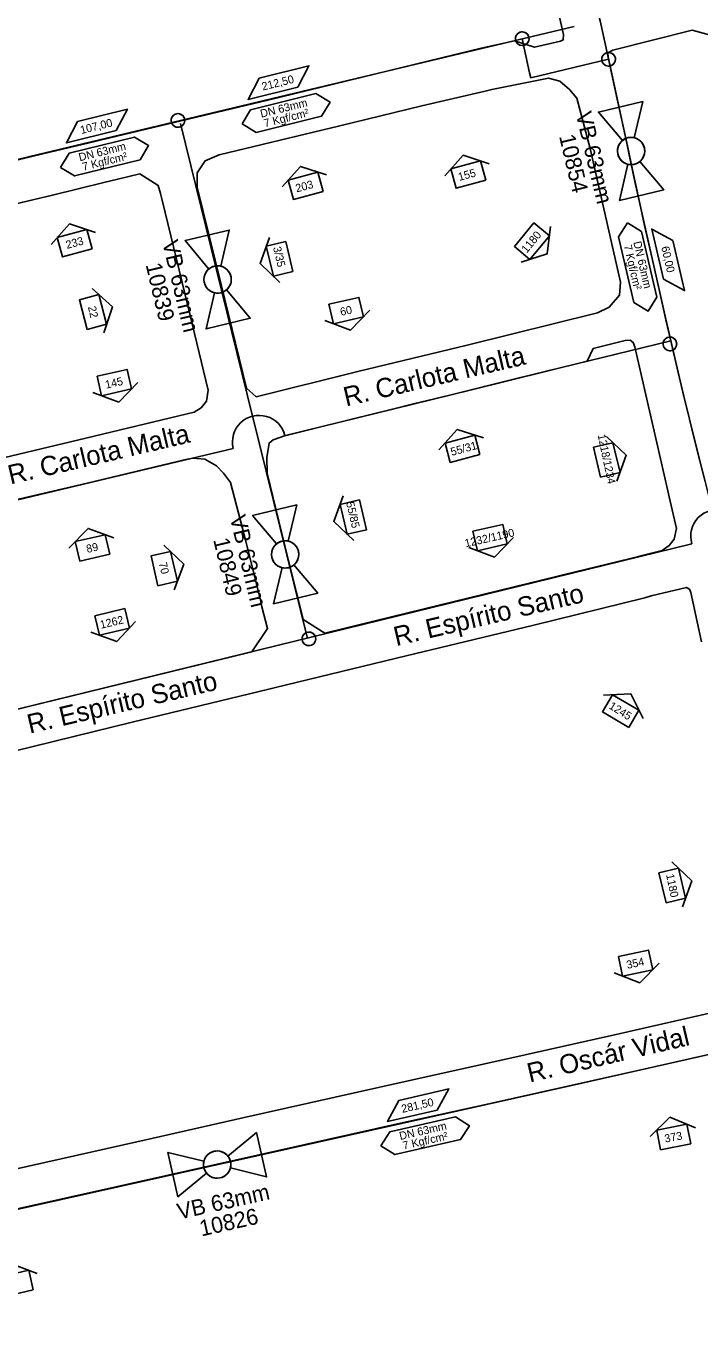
# Model space of a CAD drawing. Extents: x 656692 to 673945, y 7585994 to 7599066.
# Drawn here: x 669777.5 to 670030, y 7593096.2 to 7593583.8 of the extents above; entities that cross this region are included whole.
import ezdxf

# ---------------------------------------------------------------- set-up
doc = ezdxf.new("R2010")
doc.units = 0
for name, color, linetype in [('FORMATO', 7, 'Continuous'), ('LOGRADOURO', 7, 'Continuous'), ('LOGRADOURO_TEXTO', 7, 'Continuous'), ('NUM_REF', 7, 'Continuous'), ('SIMBOLO', 7, 'Continuous'), ('TEXTO', 7, 'Continuous'), ('TUBO_PEAD_GN_63', 7, 'Continuous'), ('VALVULA_PEAD_63', 7, 'Continuous')]:
    doc.layers.add(name, color=color, linetype=linetype)

# ---------------------------------------------------------------- blocks, each defined once
blk = doc.blocks.new('INTERLIGACAO_5')
at = {"layer": 'SIMBOLO'}
blk.add_circle((0, 0), 1.28, dxfattribs=at)
for start, end in [(0, 180), (180, 0)]:
    blk.add_arc((0, 0), 1.28, start, end, dxfattribs=at)
blk = doc.blocks.new('VALVULA_PEAD_DN_9')
at = {"layer": 'VALVULA_PEAD_63'}
for points in [[(-1.14, 0.57), (-4.25, 2.13), (-4.25, -2.13), (-1.14, -0.57)], [(-1.14, -0.57), (-4.25, -2.13), (-4.25, 2.13), (-1.14, 0.57)], [(1.14, -0.57), (4.25, -2.13), (4.25, 2.13), (1.14, 0.57)], [(1.14, -0.57), (4.25, -2.13), (4.25, 2.13), (1.14, 0.57)]]:
    blk.add_lwpolyline(points, dxfattribs=at)
blk.add_circle((0, 0), 1.28, dxfattribs=at)
for start, end in [(90, 270), (270, 90), (153.4349, 206.5651), (0, 26.5651), (333.4349, 0)]:
    blk.add_arc((0, 0), 1.28, start, end, dxfattribs=at)
blk = doc.blocks.new('NUM_REF_1')
at = {"layer": 'NUM_REF'}
blk.add_lwpolyline([(-4.3125, 0.9375), (0, 3.75), (4.3125, 0.9375)], dxfattribs=at)
blk.add_lwpolyline([(2.875, -1.875), (2.875, 1.875), (-2.875, 1.875), (-2.875, -1.875)], close=True, dxfattribs=at)

msp = doc.modelspace()

# ---------------------------------------------------------------- linework, layer by layer
at = {"layer": 'LOGRADOURO'}
msp.add_line((670024.02, 7593444.94), (670031.73, 7593414.01), dxfattribs=at)
for points in [[(669948.03, 7593575.49), (669960.57, 7593578.21), (669968.06, 7593575.91), (669977.72, 7593578.17), (669978.78, 7593578.62), (669978.93, 7593580.62), (669975.67, 7593594.92), (669968.75, 7593625.45), (669962.29, 7593653.78), (669956.77, 7593677.72)], [(670035.32, 7593580.07), (670027.12, 7593582.27), (669997.35, 7593574.79), (669995.49, 7593573.74), (669995.57, 7593572.26), (670002.69, 7593539.31), (670003.33, 7593536.19), (670005.61, 7593525.54), (670017.19, 7593473.94), (670024.02, 7593444.94)], [(669948.03, 7593575.49), (669868.09, 7593556.09), (669808.81, 7593541.9), (669803.7, 7593540.64), (669783.7, 7593535.87), (669727.87, 7593522.38), (669684.38, 7593511.95), (669669.52, 7593508.36), (669665.66, 7593502.47), (669666.03, 7593491.63), (669664.9, 7593482.8), (669665.08, 7593478.24), (669664.32, 7593475.52), (669660.45, 7593472.66), (669624.36, 7593457.72), (669596.24, 7593446.03), (669593.84, 7593445.13), (669553.2, 7593428.2), (669517.75, 7593413.5), (669482.62, 7593398.86), (669480.26, 7593397.91), (669445.74, 7593383.64)], [(669787.4, 7593520.48), (669806.67, 7593525.19), (669811.84, 7593526.44), (669820.08, 7593528.38), (669827.03, 7593524.11), (669827.88, 7593521.02), (669828.49, 7593518.5), (669838.1, 7593478.96), (669845.76, 7593447.38), (669845.13, 7593443.2), (669843.07, 7593440.74), (669840.49, 7593439.15), (669794.08, 7593428.04), (669702.99, 7593406.25)], [(669756.68, 7593513.15), (669787.4, 7593520.48)], [(669874.51, 7593389.02), (669878.75, 7593371.88), (669879.31, 7593369.48), (669881.36, 7593361.36), (669889.5, 7593356.27), (669926.7, 7593365.34), (669976.25, 7593377.5), (669978.7, 7593378.15), (670004.03, 7593384.31), (670008.81, 7593385.5), (670015.82, 7593387.26), (670018.49, 7593389.1), (670020.41, 7593391.52), (670021.19, 7593395.5), (670018.44, 7593407.32), (670017.93, 7593409.61), (670005.64, 7593463.53), (670004.99, 7593465.23), (670003.83, 7593466.08), (670001.96, 7593465.95), (669990.06, 7593463.01), (669987.75, 7593458.22), (669943.88, 7593447.4), (669908.82, 7593438.78), (669874.73, 7593430.31), (669870.08, 7593428.77), (669868.52, 7593427.51), (669867.66, 7593422.12), (669867.84, 7593416.2), (669874.51, 7593389.02)], [(669757.85, 7593402.61), (669800.32, 7593412.46), (669837.4, 7593421.41), (669839.95, 7593421.88), (669844.46, 7593421.48), (669848.81, 7593419.03), (669851.52, 7593416.22), (669854.07, 7593412.68), (669859.26, 7593393.09), (669865.29, 7593368.73), (669865.82, 7593366.19), (669867.97, 7593358.05), (669862.05, 7593349.32), (669818.71, 7593338.69), (669724.71, 7593315.68)], [(670030.61, 7593353.08), (670028.97, 7593360.56), (670026.57, 7593371.54), (670026.14, 7593372.76), (670025.03, 7593373.36), (670011.79, 7593370.25), (670009.41, 7593369.55), (669967.74, 7593359.33), (669919.87, 7593347.72), (669870.97, 7593335.89), (669868.4, 7593335.25), (669817.22, 7593322.87), (669773.04, 7593312.11)], [(670051.22, 7593217.81), (670046.35, 7593216.7), (670039.12, 7593215.13), (670000.26, 7593206.23)], [(669767.16, 7593154.07), (669825.16, 7593167.05), (669858.71, 7593174.58), (669918.4, 7593187.96), (669955.06, 7593196.1), (670000.26, 7593206.23)], [(670041.07, 7593200.06), (670010.12, 7593193.09), (669949.82, 7593179.58), (669916.63, 7593172.36), (669811.77, 7593148.88), (669773.67, 7593140.34), (669722.26, 7593128.79), (669718.22, 7593126.25), (669716.01, 7593123.86), (669713.79, 7593120.24), (669712.56, 7593115.36), (669712.92, 7593110.27), (669721.63, 7593072.67)]]:
    msp.add_lwpolyline(points, dxfattribs=at)
msp.add_lwpolyline([(669991.68, 7593476.36), (669995.99, 7593478.51), (669999.92, 7593482.9), (670000.31, 7593487.78), (669989.97, 7593532.96), (669988.83, 7593537.98), (669983.84, 7593556.77), (669981.16, 7593560.04), (669977.45, 7593563.13), (669973.31, 7593564.28), (669952.05, 7593560.03), (669949.5, 7593559.43), (669925.84, 7593553.88), (669895.02, 7593546.41), (669849.86, 7593535.6), (669844.58, 7593533.3), (669841.59, 7593528.85), (669841.55, 7593523.45), (669850.54, 7593486.95), (669860.12, 7593448.05), (669863.65, 7593444.91), (669901.82, 7593454.31), (669942.74, 7593464.24)], close=True, dxfattribs=at)
at = {"layer": 'SIMBOLO'}
for points in [[(669879.3, 7593560.96), (669860.65, 7593556.31), (669864.84, 7593564.31), (669883.49, 7593568.96)], [(669811.26, 7593544.64), (669792.62, 7593539.99), (669796.81, 7593547.99), (669815.46, 7593552.64)], [(670016.35, 7593488.97), (670011.98, 7593507.69), (670019.92, 7593503.38), (670024.29, 7593484.66)], [(669931.6, 7593177.54), (669912.87, 7593173.27), (669917.21, 7593181.18), (669935.95, 7593185.46)]]:
    msp.add_lwpolyline(points, close=True, dxfattribs=at)
for points in [[(669858.42, 7593547.12), (669861.61, 7593552.42), (669886.11, 7593558.53), (669891.41, 7593555.34), (669888.22, 7593550.04), (669863.72, 7593543.93), (669858.42, 7593547.12)], [(669790.38, 7593530.81), (669793.57, 7593536.11), (669818.07, 7593542.21), (669823.37, 7593539.03), (669820.18, 7593533.72), (669795.68, 7593527.62), (669790.38, 7593530.81)], [(670002.83, 7593510.06), (670008.08, 7593506.79), (670013.82, 7593482.2), (670010.56, 7593476.95), (670005.3, 7593480.21), (669999.56, 7593504.8), (670002.83, 7593510.06)], [(669910.45, 7593164.12), (669913.74, 7593169.36), (669938.36, 7593174.98), (669943.6, 7593171.69), (669940.3, 7593166.45), (669915.69, 7593160.83), (669910.45, 7593164.12)]]:
    msp.add_lwpolyline(points, dxfattribs=at)
at = {"layer": 'TUBO_PEAD_GN_63'}
for p, q in [((669995.78, 7593571.35), (669966.59, 7593564.39)), ((669835.34, 7593547.35), (669862.37, 7593437.6)), ((669862.28, 7593437.72), (669882.89, 7593354.26))]:
    msp.add_line(p, q, dxfattribs=at)
for points in [[(670036.5, 7593394.83), (670033.94, 7593405.1), (670031.92, 7593413.12), (670030, 7593420.91), (670028.04, 7593428.76), (670026.15, 7593436.44), (670024, 7593445.14), (670021.9, 7593454.01), (670019.78, 7593463.14), (670018.49, 7593468.48), (670017.25, 7593473.7), (670016.34, 7593477.75), (670014.68, 7593485.08), (670012.07, 7593496.69), (670009.27, 7593509.09), (670007.08, 7593519.11), (670004.85, 7593529.26), (670002.82, 7593538.9), (670000.97, 7593547.38), (669998.98, 7593556.44), (669996.99, 7593565.7), (669995.51, 7593572.61), (669992.66, 7593585.75), (669931.57, 7593813.26)], [(669982.88, 7593583.69), (669937.75, 7593572.94), (669778.87, 7593534.96), (669658.25, 7593505.45)], [(669966.59, 7593564.39), (669966.18, 7593566.29), (669963.41, 7593579.06)], [(670019.13, 7593465.83), (669972.97, 7593454.61), (669960.31, 7593451.45), (669949.23, 7593448.74), (669936.3, 7593445.5), (669922.62, 7593442.25), (669913.76, 7593440.03), (669900.04, 7593436.64), (669881.95, 7593432.15), (669874.51, 7593430.28)], [(669855.09, 7593425.5), (669813.17, 7593415.55), (669716.17, 7593392.41), (669637.81, 7593372.61)], [(670027.02, 7593389.76), (669709.48, 7593311.95), (669664.94, 7593301.21)], [(670069.84, 7593206.59), (669981.87, 7593186.76), (669716.31, 7593127.44), (669704.58, 7593124.83)]]:
    msp.add_lwpolyline(points, dxfattribs=at)
for centre, radius, start, end in [((669864.8, 7593427.9), 10, 13.7663, 193.8701), ((670036.5, 7593392.62), 9.93, 13.2191, 196.6626)]:
    msp.add_arc(centre, radius, start, end, dxfattribs=at)

# ---------------------------------------------------------------- block references
at = {"layer": 'FORMATO'}
for p, xscale, yscale, rotation in [((669943.2, 7593528.16), 2, 2, 15.171414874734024), ((669882.24, 7593523.98), 2, 2, 15.171414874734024), ((669795.72, 7593502.39), 2, 2, 15.171414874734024), ((669967.05, 7593503.2), 2, 2, -129.62750793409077), ((669872.48, 7593496.58), 2, 2, 103.25233689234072), ((669802.58, 7593476.65), 1.9999999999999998, 1.9999999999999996, -75.28274575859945), ((669897.44, 7593477.2), 2, 2, -167.17665662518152), ((669810.53, 7593450.17), 2, 2, -167.17665662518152), ((669941.03, 7593425.38), 2, 2, 15.171414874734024), ((669995.11, 7593421.2), 2, 2, -76.67539240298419), ((669900.11, 7593399.79), 2, 2, 103.25233689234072), ((669802.38, 7593388.21), 2, 2, 12.994820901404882), ((669951.37, 7593392.1), 2, 2, -167.17665662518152), ((669829.24, 7593380.49), 2, 2.0000000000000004, -77.05356600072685), ((669809.72, 7593360.51), 1.9999999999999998, 2.0000000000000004, -166.64369740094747), ((670000.31, 7593327.06), 2, 2, -30.466498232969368), ((670019.64, 7593261.72), 2, 2, -76.67539240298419), ((670005.92, 7593232.63), 2, 2, -168.20476857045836), ((670020.2, 7593167.46), 2, 2, 10.786127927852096), ((669773.72, 7593112.55), 2.0000000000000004, 1.9999999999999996, 13.244366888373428)]:
    msp.add_blockref('NUM_REF_1', p, dxfattribs=dict(at, xscale=xscale, yscale=yscale, rotation=rotation))
at = {"layer": 'SIMBOLO', "xscale": 2, "yscale": 2, "rotation": -14.764722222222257}
for p in [(669963.41, 7593579.06), (669995.78, 7593571.35), (669834.37, 7593548.42), (670018.74, 7593464.68), (669883.47, 7593354.15)]:
    msp.add_blockref('INTERLIGACAO_5', p, dxfattribs=at)
at = {"layer": 'VALVULA_PEAD_63', "xscale": 4, "yscale": 4}
for p, rotation in [((670004.21, 7593536.98), -76.6062824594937), ((669849.27, 7593488.84), -76.6062824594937), ((669874.58, 7593385.8), -76.6062824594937), ((669849.09, 7593157.1), 12.624035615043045)]:
    msp.add_blockref('VALVULA_PEAD_DN_9', p, dxfattribs=dict(at, rotation=rotation))

# ---------------------------------------------------------------- texts
for s, height, rotation, p in [('VB 63mm', 6, 283.3937, (669983.41, 7593550.94)), ('10854', 6, 283.3937, (669977.2, 7593542.52)), ('155', 3, 15.1714, (669939.85, 7593525.76)), ('203', 3, 15.1714, (669878.91, 7593521.45)), ('233', 3, 15.1714, (669792.81, 7593500.26)), ('VB 63mm', 6, 283.3937, (669828.47, 7593502.81)), ('1180', 3, 50.3725, (669965.11, 7593498.52)), ('3/35', 3, 283.2523, (669870.02, 7593500.83)), ('10839', 6, 283.3937, (669822.25, 7593494.39)), ('22', 3, 283.2129, (669800.64, 7593478.51)), ('60', 3, 12.8233, (669895.53, 7593475.17)), ('145', 3, 12.8233, (669807.49, 7593447.89)), ('1218/1234', 3, 281.8203, (669991.67, 7593430.52)), ('55/31', 3, 15.1714, (669937.02, 7593422.7)), ('55/85', 3, 283.2523, (669897.38, 7593405.17)), ('VB 63mm', 6, 283.3937, (669853.78, 7593399.76)), ('10849', 6, 283.3937, (669847.57, 7593391.34)), ('1232/1190', 3, 12.8233, (669942.22, 7593388.43)), ('89', 3, 12.9948, (669800.42, 7593386.33)), ('70', 3, 282.9464, (669827.22, 7593382.54)), ('1262', 3, 13.3563, (669805.56, 7593357.92)), ('1245', 3, 328.0292, (669995.65, 7593328.24)), ('1180', 3, 281.8203, (670017.3, 7593265.75)), ('354', 3, 11.7952, (670002.81, 7593230.45)), ('373', 3, 10.7861, (670017.04, 7593165.33)), ('VB 63mm', 6, 12.624, (669834.85, 7593136.49)), ('10826', 6, 12.624, (669843.19, 7593130.16))]:
    msp.add_text(s, height=height, rotation=rotation).set_placement(p)
at = {"layer": 'LOGRADOURO_TEXTO'}
for s, p in [('R. Carlota Malta', (669897.37, 7593441.22)), ('R. Carlota Malta', (669771.61, 7593411.98)), ('R. Espírito Santo', (669916.17, 7593351.41)), ('R. Espírito Santo', (669778.83, 7593318.58)), ('R. Oscár Vidal', (669966.19, 7593187.83))]:
    msp.add_text(s, height=7.2, rotation=13.1895, dxfattribs=at).set_placement(p)
at = {"layer": 'TEXTO'}
for s, rotation, p in [('212,50', 13.9888, (669866.22, 7593559.63)), ('DN 63mm', 13.9888, (669865.64, 7593549.44)), ('7 Kgf/cm²', 13.9888, (669867.01, 7593545.86)), ('107,00', 13.9888, (669798.18, 7593543.31)), ('DN 63mm', 13.9888, (669797.6, 7593533.12)), ('7 Kgf/cm²', 13.9888, (669798.97, 7593529.55)), ('DN 63mm', 283.1431, (670005.04, 7593502.8)), ('7 Kgf/cm²', 283.1431, (670001.44, 7593501.48)), ('60,00', 283.1431, (670015.48, 7593500.94)), ('281,50', 12.8586, (669918.5, 7593176.47)), ('DN 63mm', 12.8586, (669917.72, 7593166.3)), ('7 Kgf/cm²', 12.8586, (669919.02, 7593162.69))]:
    msp.add_text(s, height=3, rotation=rotation, dxfattribs=at).set_placement(p)

doc.saveas('drawing.dxf')
